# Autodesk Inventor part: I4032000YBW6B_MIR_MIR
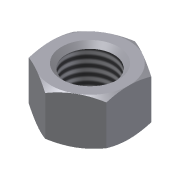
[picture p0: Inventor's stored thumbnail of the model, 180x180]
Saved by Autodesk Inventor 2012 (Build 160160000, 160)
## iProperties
Company: CAD-Verlag
Shininess: 64.0
Length Units: 11269
Angle Units: 11279
Time Units: 11290
Mass Units: 11283
Length Display Precision: 3
Angle Display Precision: 2
Compacted: True
Part Number: I4032000YBW6B_MIR_MIR
Document SubType Name: Modeling
Created: 2004-09
Material: Steel, Mild
Designer: Greiling
Manufacturer: Standard
Standards Organization: Custom
Density: 1 g/cm^3
Density: 0.0
Volumn: 0.0
Area: 0.0
PropertySet Name: Model Information
Control State: 0
Master: False
Checked Out: False
Author: Jürgen Kronas
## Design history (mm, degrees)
derived "I4032000YBW6B_MIR.ipt" dims "d64" = 0
  node "WorkPlane8"
  node "WorkPlane10"
  node "MSC_PT1"
  node "MSC_PT2"
  node "MSC_PF1"
  node "MSC_A1"
  node "WorkPoint1"
  node "WorkPoint2"
node "Volumenkörper1"
node "Volumenkörpern"
node "Oberflächenkörpern"
tag "Bezeichnung2"
feature "Volumenkörper1::I4032000YBW6B_MIR.ipt" dims "d0" = 10, "d64" = 0
